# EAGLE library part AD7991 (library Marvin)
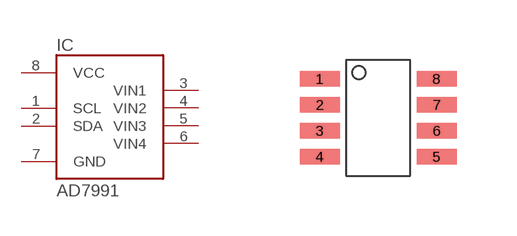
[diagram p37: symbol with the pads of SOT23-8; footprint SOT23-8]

Designator prefix IC

## AD7991  [SOT23-8]
1  SCL
2  SDA
3  VIN1  in
4  VIN2  in
5  VIN3  in
6  VIN4  in
7  GND  pwr
8  VCC  pwr

## Footprint SOT23-8 (pad centres in mm)
smd 1 x 0.38: 1 -1.462,0.975; 2 -1.462,0.325; 3 -1.462,-0.325; 4 -1.462,-0.975; 5 1.462,-0.975; 6 1.462,-0.325; 7 1.462,0.325; 8 1.462,0.975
